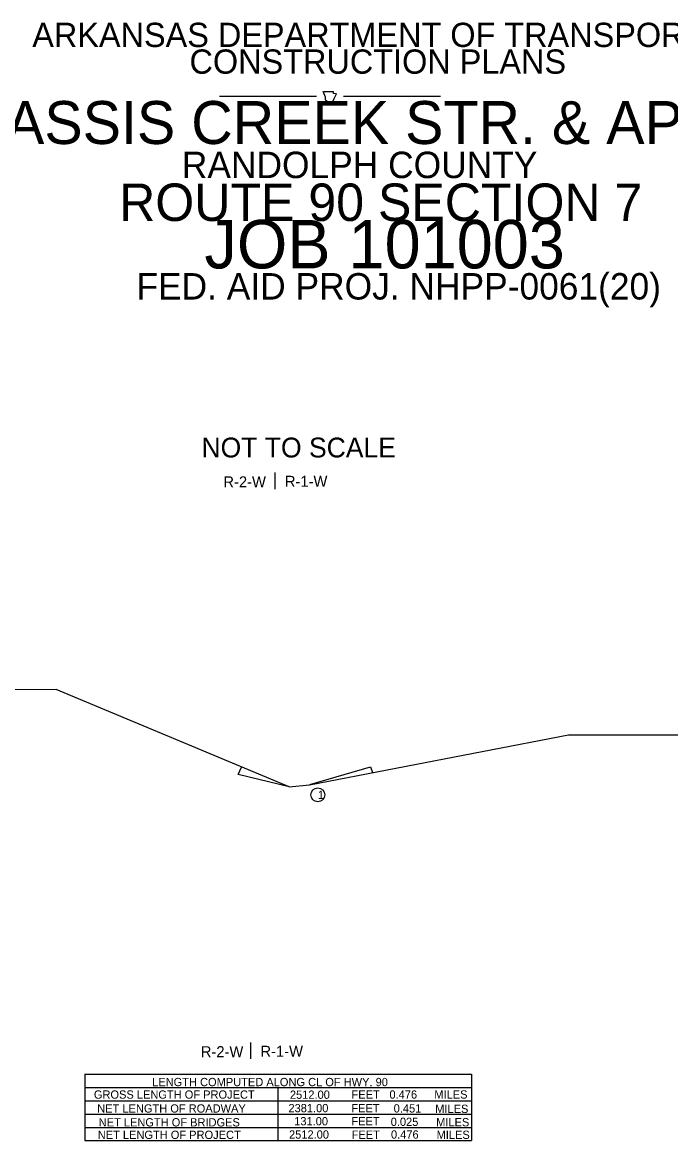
# Model space of a CAD drawing. Extents: x 152 to 3426, y 67 to 2142.
# Drawn here: x 1270 to 2447, y 68 to 2098 of the extents above; entities that cross this region are included whole.
import ezdxf

# ---------------------------------------------------------------- set-up
doc = ezdxf.new("R2010")
doc.units = 0
for name, color, linetype in [('Default', 7, 'Continuous'), ('R_Border', 7, 'Continuous'), ('R_Grid', 7, 'Continuous'), ('S_AREA_CALC', 7, 'Continuous')]:
    doc.layers.add(name, color=color, linetype=linetype)

msp = doc.modelspace()

# ---------------------------------------------------------------- linework, layer by layer
at = {"layer": 'Default'}
for p, q in [((1728.8, 1280.5), (1728.8, 1250.8)), ((1684.5, 246), (1684.5, 216.3))]:
    msp.add_line(p, q, dxfattribs=at)
for points in [[(1754.5, 710), (1331.7, 886.8), (728.8, 886.4)], [(1791.6, 713.9), (2261.8, 804.9), (2787.2, 804.6)], [(1754.5, 710), (1662, 732.5), (1667.8, 746.2)], [(1792.1, 714.5), (1902.4, 746.3), (1905.8, 736)]]:
    msp.add_lwpolyline(points, dxfattribs=at)
at = {"layer": 'R_Border'}
msp.add_circle((1806.7, 695.6), 12.6, dxfattribs=at)
at = {"layer": 'R_Grid'}
for p, q in [((1383.7, 188.4), (1383.7, 68.1)), ((1383.7, 188.4), (2085.4, 188.4)), ((2085.4, 188.4), (2085.4, 68.1)), ((1383.7, 164.3), (2085.4, 164.3)), ((1733.9, 164.3), (1733.9, 68.1)), ((1383.7, 140.3), (2085.4, 140.3)), ((1383.7, 116.2), (2085.4, 116.2)), ((1383.7, 92.1), (2085.4, 92.1)), ((1383.7, 68.1), (2085.4, 68.1))]:
    msp.add_line(p, q, dxfattribs=at)
at = {"layer": 'S_AREA_CALC'}
for p, q in [((1628.3, 1963.8), (1804.4, 1963.8)), ((1853.3, 1963.8), (2029.4, 1963.8)), ((1754.5, 710), (1791.6, 713.9))]:
    msp.add_line(p, q, dxfattribs=at)
msp.add_lwpolyline([(1815.8, 1972.7), (1819.6, 1962.9), (1819.6, 1956.9), (1822.6, 1956.2), (1822.6, 1954), (1833.7, 1954), (1836, 1959.9), (1840.5, 1968.2), (1835.2, 1968.8), (1835.2, 1971.9), (1816.6, 1971.9)], dxfattribs=at)

# ---------------------------------------------------------------- texts
at = {"layer": 'Default'}
for s, p in [('R-2-W', (1635.1, 1253.8)), ('R-1-W', (1746.7, 1254.8)), ('R-2-W', (1594.1, 219.5)), ('R-1-W', (1702.4, 220.3))]:
    msp.add_text(s, height=20, dxfattribs=at).set_placement(p)
at = {"layer": 'R_Border'}
for s, height, p in [('ARKANSAS DEPARTMENT OF TRANSPORTATION', 44.03, (1288.1, 2053.1)), ('CONSTRUCTION PLANS', 44.03, (1573.6, 2004.6)), ('EASSIS CREEK STR. & APPRS. (S)', 78, (1170.9, 1877)), ('RANDOLPH COUNTY', 48, (1559.7, 1815.1)), ('ROUTE 90 SECTION 7', 68, (1445.8, 1737.3)), ('JOB 101003', 88, (1600.8, 1651.2)), ('NOT TO SCALE', 36, (1595.3, 1308.1)), ('1', 15, (1806.7, 688.1))]:
    msp.add_text(s, height=height, dxfattribs=at).set_placement(p)
at = {"layer": 'R_Grid'}
for s, p in [('LENGTH COMPUTED ALONG CL OF HWY. 90', (1505.8, 166.9)), ('GROSS LENGTH OF PROJECT', (1400, 144.2)), ('2512.00', (1755.9, 144)), ('FEET', (1867.7, 144.2)), ('0.476', (1936.6, 144.3)), ('MILES', (2018.1, 144.4)), ('NET LENGTH OF ROADWAY', (1406.1, 119)), ('2381.00', (1753.2, 119.6)), ('FEET', (1867.5, 119.3)), ('0.451', (1944.3, 119.1)), ('MILES', (2019.7, 118.3)), ('NET LENGTH OF BRIDGES', (1408.7, 93.8)), ('131.00', (1763.7, 95.8)), ('FEET', (1867.6, 95.8)), ('0.025', (1938.9, 94.7)), ('MILES', (2021.4, 94)), ('NET LENGTH OF PROJECT', (1407, 71.1)), ('2512.00', (1754.3, 71.7)), ('FEET', (1867.9, 71.3)), ('0.476', (1939.4, 71.7)), ('MILES', (2022.2, 71.2))]:
    msp.add_text(s, height=15, dxfattribs=at).set_placement(p)
at = {"layer": 'S_AREA_CALC'}
msp.add_text('FED. AID PROJ. NHPP-0061(20)', height=48, dxfattribs=at).set_placement((1477.2, 1594.7))

doc.saveas('drawing.dxf')
